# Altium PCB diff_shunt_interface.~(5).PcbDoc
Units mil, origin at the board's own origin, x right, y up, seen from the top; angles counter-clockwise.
Board outline 420 x 600 mil, 2 copper layers (Top Layer, Bottom Layer), stack 16.1 mil thick; 5 components, 6 nets, 12 pads, 2 vias.
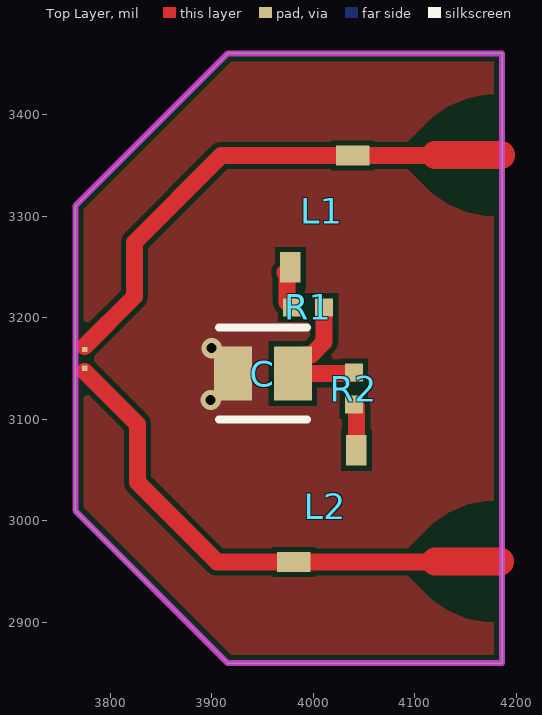
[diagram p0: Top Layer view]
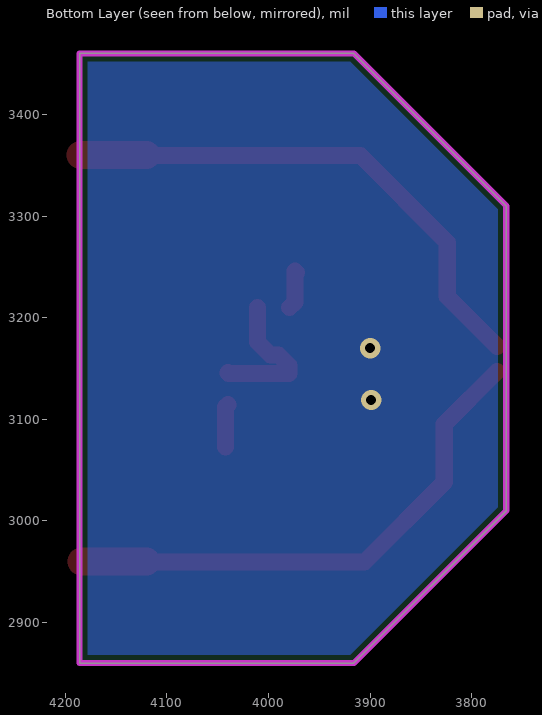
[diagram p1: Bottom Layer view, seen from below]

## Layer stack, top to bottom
Top Solder: solder mask 0.4, Solder Resist, Dk 3.5
Top Layer: signal copper 1.4
Dielectric 1: dielectric 13.3, FR-4, Dk 3.66
Bottom Layer: signal copper 1.4
Bottom Solder: solder mask 0.4, Solder Resist, Dk 3.5

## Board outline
3766,3010 3916,2860 4186,2860 4186,3460 3916,3460 3766,3310

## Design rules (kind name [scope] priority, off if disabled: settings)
Clearance Clearance_1 [InNet('No Net') vs InNet('GND')] p1: gap=50 ignorepadtopadclearanceinfootprint=FALSE except(0: Arc-Hole Track-Hole SMDPad-Hole THPad-Hole Via-Hole Fill-Hole Poly-Hole Region-Hole Text-Hole)
Clearance [All] p2: gap=5 ignorepadtopadclearanceinfootprint=FALSE except(0: Arc-Hole Track-Hole SMDPad-Hole THPad-Hole Via-Hole Fill-Hole Poly-Hole Region-Hole Text-Hole)
PolygonConnect [All] p1: connectstyle=Direct reliefconductorwidth=10 reliefentries=4 polygonreliefangle="90 Angle" airgapwidth=10
RoutingVias [All] p1: holewidth=28 width=50 viastyle="Through Hole" minholewidth=28 minwidth=50 maxholewidth=28 maxwidth=50
SolderMaskExpansion [All] p1: expansion=4 istentingtop=FALSE
Width [All] p1: maxlimit=50 minlimit=16.82 preferedwidth=16.82 impedanceprofiledriven=TRUE impedanceprofileid={C9EE0A32-63B8-435B-8C3B-82C28B80C81C} impedanceprofilevalue=50.000000 minimp=50.000000 maximp=50.000000 favimp=50.000000
30 further rules are at their usual default settings.

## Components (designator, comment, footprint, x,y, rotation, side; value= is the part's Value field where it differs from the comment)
C "CBR08C470FAGAC" FP-CBR08C-MFG 3950.47,3145 r0 top value="47 pF"
L1 "506WLSM0R70KT619T" 506WLS 4005,3307 r180 top
L2 "506WLSM0R70KT619T" 506WLS 4015,3012 r0 top
R1 "50R 0402" RESC1005X35X20LL05T10 3995,3210 r180 top
R2 "50R 0402" RESC1005X35X20LL05T10 4040,3130 r90 top

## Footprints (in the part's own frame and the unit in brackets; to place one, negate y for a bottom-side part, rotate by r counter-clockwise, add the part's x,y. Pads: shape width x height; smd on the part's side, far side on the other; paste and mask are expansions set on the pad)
506WLS [mil] "ATC conical inductor"
  rect 20x30 smd mask+1.97: 1(27.5,57.5)
  rect 33x20 smd mask+1.97: 2(-34,-52.5)
  body extent -45,-58 35,69, height 105
FP-CBR08C-MFG [mm]
  rect 0.95x1.35 smd paste+0 mask+0: 1(-0.75,0) 2(0.75,0)
  silkscreen extent -1.1,-1.15 1.1,1.15, body extent -1.4,-0.85 1.4,0.85, height 0.25
RESC1005X35X20LL05T10 [mm] "Chip Resistor, 2-Leads, Body 1.00x0.50mm, IPC High Density"
  rect 0.45x0.45 smd: 1(-0.4,0) 2(0.4,0)
  body extent -0.53,-0.27 0.53,0.28, height 0.35

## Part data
C: library part CMP-03020-025427-1, "CAP CER 47PF 250V C0G/NP0 0805", Capacitance="47 pF", Manufacturer=KEMET, Package=CBR08C, Temperature="-55°C to +125°C", Temperature Characteristic=C0G, Temperature Coefficient=30ppm/°C, Temperature Range High=+125°C, Temperature Range Low=-55°C, Tolerance=0.01, Voltage Rating="250 V"
L1 L2: "coilcraft 700nH"
R1 R2: library part CMP-2002-03144-1, Manufacturer="TE Connectivity / AMP", Part Number=CPF0402B15K8E1

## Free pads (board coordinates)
  rect 5.12x5.12 smd: 2(3775.06,3150.16) 3(3775.06,3168.66)

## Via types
v1: diameter 20, hole 10, Top Layer to Bottom Layer, 2 vias

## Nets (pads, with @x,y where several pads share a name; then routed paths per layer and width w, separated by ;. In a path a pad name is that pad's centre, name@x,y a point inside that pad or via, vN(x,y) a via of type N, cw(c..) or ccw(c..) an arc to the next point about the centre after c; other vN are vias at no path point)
GND: C.1
  other v1: 3899,3119 3900,3170
NetC_2: C.2 R1.1 R2.2 | length 142.6
  Top Layer w16.82: R1.1 4010.75,3175.92 3998,3163.17 3990.29,3163.17 3980,3152.87 C.2 4039.25,3145 R2.2
NetL1_1: L1.1 R1.2 | length 40.3
  Top Layer w16.82: L1.1@3972.5,3244.5 L1.1@3974.09,3242.91 ; L1.1@3974.09,3245.91 3974.09,3215.16 R1.2
NetL1_2: L1.2 pad.3 | length 453.9
  Top Layer w16.82: 3775.06,3171.81 3824.07,3220.83 3824.07,3274.07 3909.5,3359.5 L1.2 4120,3359.5
NetL2_1: L2.1 R2.1 | length 42.8
  Top Layer w16.82: R2.1 4042.5,3111.75 L2.1@4042.5,3072.5
NetL2_2: L2.2 pad.2 | length 456
  Top Layer w16.82: 3775.06,3147.01 3827.02,3095.04 3827.02,3037.98 3905.5,2959.5 L2.2 4120,2959.5
copper on no net: | length 129
  Top Layer w27.3: 4120,2960 4184,2960 ; 4120,3360 4185,3360

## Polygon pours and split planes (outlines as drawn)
GND on Bottom Layer "Bottom Layer-No Net" (solid, pour order 0): 3766,3310 3916,3460 4186,3460 4186,2860 3916,2860 3766,3010
GND on Top Layer "GND_L01_P001" (solid, pour order 1): 3767,3011 3917,2861 4187,2861 4187,3461 3917,3461 3767,3311
no net on Top Solder "NONET_L01_P002" (solid, pour order 2): 3766,3010 3916,2860 4186,2860 4186,3460 3916,3460 3766,3310
no net on Bottom Solder (solid, pour order 3): 3766,3010 3916,2860 4186,2860 4186,3460 3916,3460 3766,3310

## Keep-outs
Keep-Out Layer:
  the board outline again, w6

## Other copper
Top Layer:
  pour cut-out: 4079.5,2959.5 4110.71,2990.71 cw(c4181.42,2920) 4181.42,3020 4190,3020 4190,2900 4180.42,2900 cw(c4180.42,3000) 4109.71,2929.29
  pour cut-out: 4079.5,3359.5 4110.71,3390.71 cw(c4181.42,3320) 4181.42,3420 4190,3420 4190,3300 4180.42,3300 cw(c4180.42,3400) 4109.71,3329.29

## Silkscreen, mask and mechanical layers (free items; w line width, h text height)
Top Solder:
  lines w27.3: 4120,2960 4185,2960 ; 4120.5,3360 4185.5,3360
